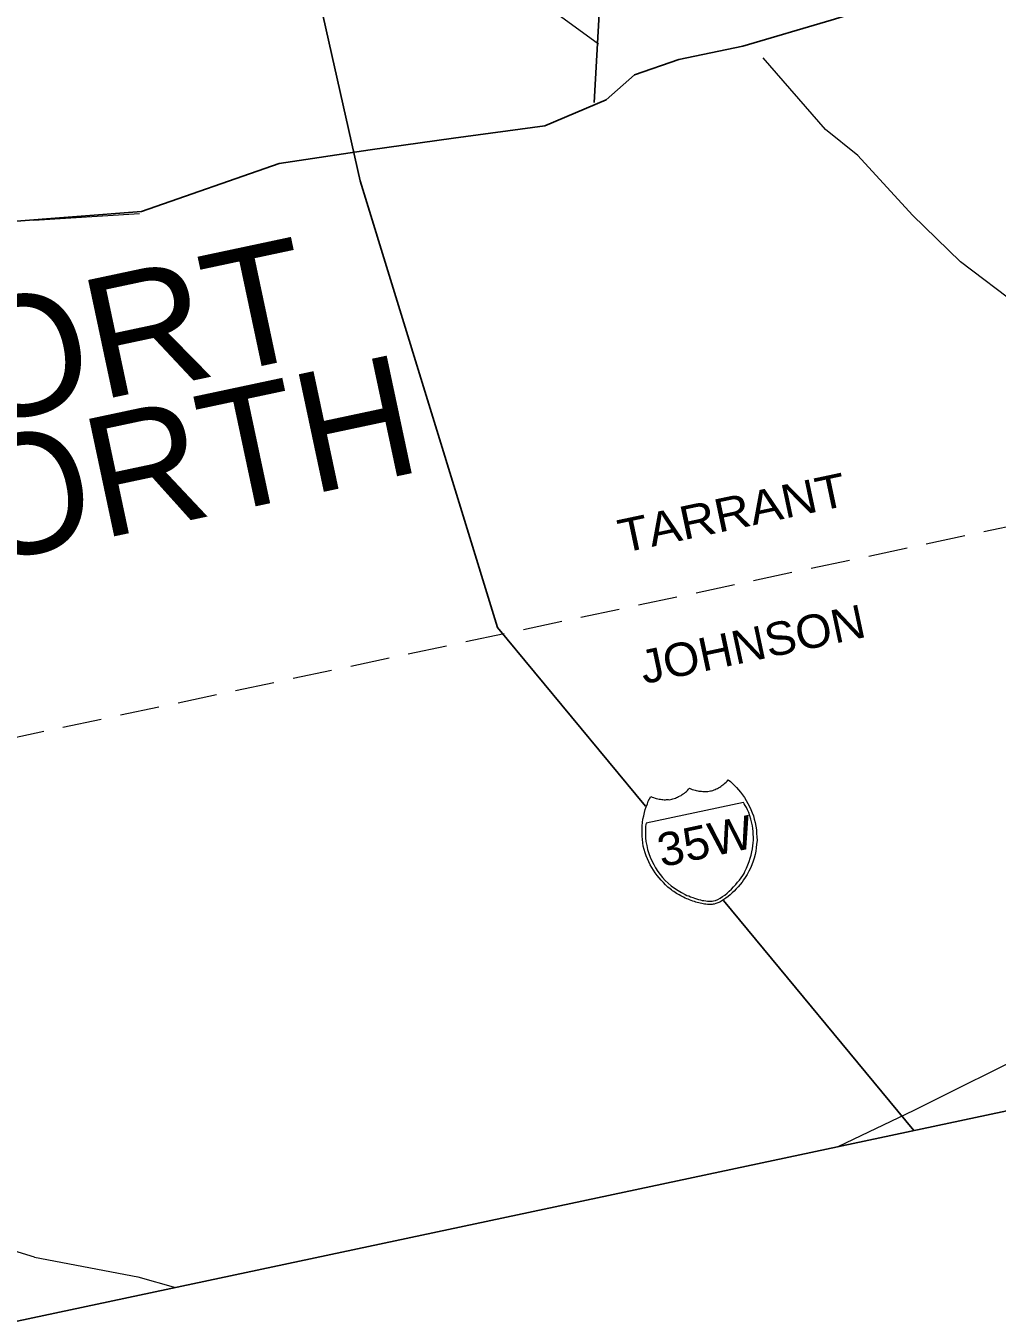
# Model space of a CAD drawing. Extents: x 2357218 to 2371708, y 6973728 to 6980157.
# Drawn here: x 2371385.2 to 2371533.8, y 6977387.6 to 6977585.2 of the extents above; entities that cross this region are included whole.
import ezdxf

# ---------------------------------------------------------------- set-up
doc = ezdxf.new("R2010")
doc.units = 0
doc.header["$LTSCALE"] = 2
doc.linetypes.add('MEDIUM_DASHED', pattern=[4.5, 3, -1.5])
doc.layers.add('62', color=7, linetype='Continuous', lineweight=13)
doc.layers.add('63', color=7, linetype='Continuous', lineweight=13)

msp = doc.modelspace()

# ---------------------------------------------------------------- linework, layer by layer
at = {"layer": '62', "lineweight": 25}
for p, q in [((2371472.934, 6977588.003), (2371472.125, 6977573.525)), ((2371491.914, 6977451.41), (2371521.051, 6977416.173))]:
    msp.add_line(p, q, dxfattribs=at)
at = {"layer": '62'}
for p, q in [((2371402.615, 6977556.471), (2371386.454, 6977555.453)), ((2371386.545, 6977396.784), (2371375.178, 6977400.278))]:
    msp.add_line(p, q, dxfattribs=at)
at = {"layer": '62', "linetype": 'MEDIUM_DASHED'}
msp.add_line((2371250.037, 6977447.964), (2371689.806, 6977541.441), dxfattribs=at)
at = {"layer": '62', "lineweight": 25}
for points in [[(2371171.482, 6977817.538), (2371268.218, 6977362.432), (2371707.985, 6977455.907), (2371611.249, 6977911.015)], [(2371413.016, 6977663.491), (2371424.115, 6977615.928), (2371436.376, 6977561.509), (2371457.345, 6977493.157), (2371479.97, 6977465.828)], [(2371525.33, 6977592.147), (2371517.989, 6977589.024), (2371508.4, 6977586.087), (2371494.884, 6977582.133), (2371485.112, 6977580.058), (2371478.295, 6977577.711), (2371473.995, 6977573.922), (2371464.607, 6977569.925), (2371450.652, 6977568.04), (2371437.897, 6977566.249), (2371423.963, 6977564.162), (2371402.89, 6977556.805), (2371381.813, 6977555.202), (2371364.473, 6977555.496), (2371353.545, 6977558.763), (2371347.781, 6977571.044), (2371345.031, 6977583.983), (2371341.826, 6977589.973), (2371344.749, 6977600.141)]]:
    msp.add_lwpolyline(points, dxfattribs=at)
at = {"layer": '62'}
for points in [[(2371472.829, 6977582.438), (2371452.543, 6977597.245), (2371424.668, 6977617.014)], [(2371640.114, 6977493.057), (2371631.587, 6977494.329), (2371621.782, 6977494.129), (2371604.117, 6977494.011), (2371592.783, 6977497.996), (2371585.105, 6977500.871), (2371575.158, 6977504.807), (2371564.602, 6977512.159), (2371556.475, 6977520.853), (2371548.287, 6977530.798), (2371537.195, 6977542.291), (2371528.149, 6977549.131), (2371520.811, 6977556.266), (2371512.448, 6977565.414), (2371507.538, 6977569.364), (2371497.978, 6977580.353)], [(2371641.471, 6977568.825), (2371637.889, 6977558.952), (2371632.104, 6977540.699), (2371630.059, 6977521.101), (2371629.958, 6977506.428), (2371616.354, 6977490.125), (2371618.311, 6977480.254), (2371604.289, 6977467.66), (2371593.247, 6977456.295), (2371579.034, 6977445.889), (2371557.99, 6977437.089), (2371540.234, 6977428.852), (2371521.019, 6977419.249), (2371509.386, 6977413.693)], [(2371487.57, 6977468.272), (2371487.767, 6977468.22), (2371487.983, 6977468.173), (2371488.151, 6977468.142), (2371488.368, 6977468.096), (2371488.575, 6977468.093), (2371488.765, 6977468.066), (2371488.95, 6977468.059), (2371489.152, 6977468.079), (2371489.338, 6977468.073), (2371489.547, 6977468.07), (2371489.723, 6977468.108), (2371489.922, 6977468.15), (2371490.097, 6977468.186), (2371490.271, 6977468.224), (2371490.482, 6977468.316), (2371490.628, 6977468.391), (2371490.799, 6977468.452), (2371490.987, 6977468.536), (2371491.172, 6977468.647), (2371491.339, 6977468.727), (2371491.518, 6977468.856), (2371491.68, 6977468.959), (2371491.838, 6977469.085), (2371491.995, 6977469.21), (2371492.153, 6977469.336), (2371492.326, 6977469.489), (2371492.496, 6977469.664), (2371492.646, 6977469.833), (2371492.973, 6977469.582), (2371493.288, 6977469.303), (2371493.604, 6977469.002), (2371493.928, 6977468.657), (2371494.231, 6977468.33), (2371494.539, 6977467.959), (2371494.832, 6977467.56), (2371495.128, 6977467.139), (2371495.407, 6977466.695), (2371495.664, 6977466.242), (2371495.901, 6977465.763), (2371496.115, 6977465.304), (2371496.311, 6977464.816), (2371496.507, 6977464.328), (2371496.638, 6977463.826), (2371496.791, 6977463.329), (2371496.863, 6977462.77), (2371496.956, 6977462.213), (2371496.987, 6977461.645), (2371497.026, 6977461.124), (2371497.053, 6977460.577), (2371496.989, 6977460.012), (2371496.942, 6977459.471), (2371496.869, 6977458.951), (2371496.751, 6977458.418), (2371496.613, 6977457.885), (2371496.443, 6977457.387), (2371496.275, 6977456.868), (2371496.04, 6977456.358), (2371495.796, 6977455.871), (2371495.535, 6977455.376), (2371495.222, 6977454.897), (2371495.001, 6977454.528), (2371494.755, 6977454.178), (2371494.462, 6977453.816), (2371494.187, 6977453.481), (2371493.865, 6977453.16), (2371493.541, 6977452.838), (2371493.236, 6977452.542), (2371492.932, 6977452.248), (2371492.622, 6977451.976), (2371492.303, 6977451.745), (2371491.984, 6977451.517), (2371491.662, 6977451.31), (2371491.369, 6977451.156), (2371491.076, 6977451.026), (2371490.776, 6977450.916), (2371490.517, 6977450.836)], [(2371490.517, 6977450.836), (2371490.336, 6977450.823), (2371490.183, 6977450.79), (2371490.003, 6977450.773), (2371489.841, 6977450.786), (2371489.653, 6977450.793), (2371489.468, 6977450.798), (2371489.233, 6977450.818), (2371489.02, 6977450.84), (2371488.827, 6977450.891), (2371488.615, 6977450.917), (2371488.369, 6977450.978), (2371488.152, 6977451.024), (2371487.914, 6977451.067), (2371487.717, 6977451.138), (2371487.466, 6977451.225), (2371487.223, 6977451.288), (2371486.998, 6977451.378), (2371486.748, 6977451.464), (2371486.52, 6977451.575), (2371486.293, 6977451.663), (2371486.065, 6977451.755), (2371485.832, 6977451.889), (2371485.604, 6977451.979), (2371485.395, 6977452.096), (2371485.16, 6977452.23), (2371484.951, 6977452.346), (2371484.743, 6977452.461), (2371484.551, 6977452.606), (2371484.316, 6977452.74), (2371484.129, 6977452.859), (2371483.958, 6977453.009), (2371483.768, 6977453.153), (2371483.429, 6977453.449), (2371483.052, 6977453.807), (2371482.728, 6977454.15), (2371482.403, 6977454.496), (2371482.072, 6977454.862), (2371481.762, 6977455.232), (2371481.475, 6977455.608), (2371481.227, 6977456.017), (2371480.957, 6977456.42), (2371480.705, 6977456.849), (2371480.513, 6977457.315), (2371480.306, 6977457.754), (2371480.091, 6977458.214), (2371479.95, 6977458.669), (2371479.794, 6977459.188), (2371479.661, 6977459.688), (2371479.6, 6977460.207), (2371479.536, 6977460.721), (2371479.495, 6977461.241), (2371479.473, 6977461.766), (2371479.482, 6977462.274), (2371479.507, 6977462.808), (2371479.557, 6977463.324), (2371479.609, 6977463.842), (2371479.731, 6977464.351), (2371479.833, 6977464.833), (2371479.966, 6977465.297), (2371480.105, 6977465.719), (2371480.287, 6977466.174), (2371480.41, 6977466.564), (2371480.604, 6977466.951), (2371480.802, 6977467.316), (2371481.006, 6977467.222), (2371481.232, 6977467.131), (2371481.456, 6977467.062), (2371481.65, 6977467.011), (2371481.867, 6977466.965), (2371482.061, 6977466.917), (2371482.273, 6977466.891), (2371482.469, 6977466.842), (2371482.653, 6977466.836), (2371482.843, 6977466.807), (2371483.05, 6977466.805), (2371483.231, 6977466.819), (2371483.463, 6977466.824), (2371483.625, 6977466.811), (2371483.801, 6977466.848), (2371484.02, 6977466.896), (2371484.196, 6977466.933), (2371484.372, 6977466.97), (2371484.561, 6977467.056), (2371484.727, 6977467.137), (2371484.899, 6977467.198), (2371485.065, 6977467.279), (2371485.272, 6977467.393), (2371485.441, 6977467.473), (2371485.598, 6977467.599), (2371485.76, 6977467.703), (2371485.939, 6977467.833), (2371486.118, 6977467.963), (2371486.275, 6977468.089), (2371486.428, 6977468.235), (2371486.578, 6977468.404), (2371486.746, 6977468.578), (2371486.95, 6977468.485), (2371487.154, 6977468.39), (2371487.377, 6977468.323), (2371487.57, 6977468.272)], [(2371386.545, 6977396.784), (2371402.342, 6977393.793), (2371408.116, 6977392.167)]]:
    msp.add_lwpolyline(points, dxfattribs=at)
msp.add_lwpolyline([(2371494.987, 6977466.398), (2371480.084, 6977463.229), (2371480.045, 6977462.992), (2371480.016, 6977462.687), (2371479.993, 6977462.361), (2371479.99, 6977461.943), (2371479.974, 6977461.48), (2371479.993, 6977460.957), (2371480.06, 6977460.419), (2371480.19, 6977459.799), (2371480.32, 6977459.207), (2371480.499, 6977458.576), (2371480.713, 6977458.002), (2371480.971, 6977457.435), (2371481.251, 6977456.873), (2371481.544, 6977456.361), (2371481.864, 6977455.83), (2371482.24, 6977455.358), (2371482.612, 6977454.909), (2371483.007, 6977454.463), (2371483.467, 6977454.031), (2371483.92, 6977453.623), (2371484.432, 6977453.272), (2371484.966, 6977452.923), (2371485.49, 6977452.62), (2371486.059, 6977452.329), (2371486.321, 6977452.176), (2371486.618, 6977452.078), (2371486.902, 6977451.932), (2371487.221, 6977451.838), (2371487.498, 6977451.735), (2371487.797, 6977451.617), (2371488.085, 6977451.564), (2371488.382, 6977451.465), (2371488.669, 6977451.41), (2371488.93, 6977451.375), (2371489.22, 6977451.32), (2371489.458, 6977451.279), (2371489.734, 6977451.268), (2371489.964, 6977451.272), (2371490.19, 6977451.298), (2371490.416, 6977451.323), (2371490.72, 6977451.41), (2371491.078, 6977451.554), (2371491.402, 6977451.761), (2371491.771, 6977451.979), (2371492.11, 6977452.211), (2371492.465, 6977452.495), (2371492.794, 6977452.794), (2371493.138, 6977453.118), (2371493.478, 6977453.469), (2371493.791, 6977453.834), (2371494.088, 6977454.172), (2371494.362, 6977454.506), (2371494.637, 6977454.84), (2371494.861, 6977455.188), (2371495.064, 6977455.531), (2371495.189, 6977455.811), (2371495.443, 6977456.348), (2371495.635, 6977456.849), (2371495.827, 6977457.348), (2371495.993, 6977457.866), (2371496.146, 6977458.338), (2371496.254, 6977458.821), (2371496.34, 6977459.274), (2371496.401, 6977459.748), (2371496.464, 6977460.199), (2371496.509, 6977460.644), (2371496.51, 6977461.083), (2371496.481, 6977461.535), (2371496.456, 6977461.969), (2371496.413, 6977462.396), (2371496.345, 6977462.821), (2371496.261, 6977463.215), (2371496.129, 6977463.834), (2371495.974, 6977464.351), (2371495.778, 6977464.841), (2371495.619, 6977465.265), (2371495.425, 6977465.639), (2371495.247, 6977465.925), (2371495.099, 6977466.192)], close=True, dxfattribs=at)
at = {"layer": '63', "lineweight": 25}
for p, q in [((2371472.934, 6977588.003), (2371472.125, 6977573.525)), ((2371491.914, 6977451.41), (2371521.051, 6977416.173))]:
    msp.add_line(p, q, dxfattribs=at)
at = {"layer": '63'}
for p, q in [((2371402.615, 6977556.471), (2371386.454, 6977555.453)), ((2371386.545, 6977396.784), (2371375.178, 6977400.278))]:
    msp.add_line(p, q, dxfattribs=at)
at = {"layer": '63', "linetype": 'MEDIUM_DASHED'}
msp.add_line((2371250.037, 6977447.964), (2371689.806, 6977541.441), dxfattribs=at)
at = {"layer": '63', "lineweight": 25}
for points in [[(2371171.482, 6977817.538), (2371268.218, 6977362.432), (2371707.985, 6977455.907), (2371611.249, 6977911.015)], [(2371413.016, 6977663.491), (2371424.115, 6977615.928), (2371436.376, 6977561.509), (2371457.345, 6977493.157), (2371479.97, 6977465.828)], [(2371525.33, 6977592.147), (2371517.989, 6977589.024), (2371508.4, 6977586.087), (2371494.884, 6977582.133), (2371485.112, 6977580.058), (2371478.295, 6977577.711), (2371473.995, 6977573.922), (2371464.607, 6977569.925), (2371450.652, 6977568.04), (2371437.897, 6977566.249), (2371423.963, 6977564.162), (2371402.89, 6977556.805), (2371381.813, 6977555.202), (2371364.473, 6977555.496), (2371353.545, 6977558.763), (2371347.781, 6977571.044), (2371345.031, 6977583.983), (2371341.826, 6977589.973), (2371344.749, 6977600.141)]]:
    msp.add_lwpolyline(points, dxfattribs=at)
at = {"layer": '63'}
for points in [[(2371472.829, 6977582.438), (2371452.543, 6977597.245), (2371424.668, 6977617.014)], [(2371640.114, 6977493.057), (2371631.587, 6977494.329), (2371621.782, 6977494.129), (2371604.117, 6977494.011), (2371592.783, 6977497.996), (2371585.105, 6977500.871), (2371575.158, 6977504.807), (2371564.602, 6977512.159), (2371556.475, 6977520.853), (2371548.287, 6977530.798), (2371537.195, 6977542.291), (2371528.149, 6977549.131), (2371520.811, 6977556.266), (2371512.448, 6977565.414), (2371507.538, 6977569.364), (2371497.978, 6977580.353)], [(2371641.471, 6977568.825), (2371637.889, 6977558.952), (2371632.104, 6977540.699), (2371630.059, 6977521.101), (2371629.958, 6977506.428), (2371616.354, 6977490.125), (2371618.311, 6977480.254), (2371604.289, 6977467.66), (2371593.247, 6977456.295), (2371579.034, 6977445.889), (2371557.99, 6977437.089), (2371540.234, 6977428.852), (2371521.019, 6977419.249), (2371509.386, 6977413.693)], [(2371487.57, 6977468.272), (2371487.767, 6977468.22), (2371487.983, 6977468.173), (2371488.151, 6977468.142), (2371488.368, 6977468.096), (2371488.575, 6977468.093), (2371488.765, 6977468.066), (2371488.95, 6977468.059), (2371489.152, 6977468.079), (2371489.338, 6977468.073), (2371489.547, 6977468.07), (2371489.723, 6977468.108), (2371489.922, 6977468.15), (2371490.097, 6977468.186), (2371490.271, 6977468.224), (2371490.482, 6977468.316), (2371490.628, 6977468.391), (2371490.799, 6977468.452), (2371490.987, 6977468.536), (2371491.172, 6977468.647), (2371491.339, 6977468.727), (2371491.518, 6977468.856), (2371491.68, 6977468.959), (2371491.838, 6977469.085), (2371491.995, 6977469.21), (2371492.153, 6977469.336), (2371492.326, 6977469.489), (2371492.496, 6977469.664), (2371492.646, 6977469.833), (2371492.973, 6977469.582), (2371493.288, 6977469.303), (2371493.604, 6977469.002), (2371493.928, 6977468.657), (2371494.231, 6977468.33), (2371494.539, 6977467.959), (2371494.832, 6977467.56), (2371495.128, 6977467.139), (2371495.407, 6977466.695), (2371495.664, 6977466.242), (2371495.901, 6977465.763), (2371496.115, 6977465.304), (2371496.311, 6977464.816), (2371496.507, 6977464.328), (2371496.638, 6977463.826), (2371496.791, 6977463.329), (2371496.863, 6977462.77), (2371496.956, 6977462.213), (2371496.987, 6977461.645), (2371497.026, 6977461.124), (2371497.053, 6977460.577), (2371496.989, 6977460.012), (2371496.942, 6977459.471), (2371496.869, 6977458.951), (2371496.751, 6977458.418), (2371496.613, 6977457.885), (2371496.443, 6977457.387), (2371496.275, 6977456.868), (2371496.04, 6977456.358), (2371495.796, 6977455.871), (2371495.535, 6977455.376), (2371495.222, 6977454.897), (2371495.001, 6977454.528), (2371494.755, 6977454.178), (2371494.462, 6977453.816), (2371494.187, 6977453.481), (2371493.865, 6977453.16), (2371493.541, 6977452.838), (2371493.236, 6977452.542), (2371492.932, 6977452.248), (2371492.622, 6977451.976), (2371492.303, 6977451.745), (2371491.984, 6977451.517), (2371491.662, 6977451.31), (2371491.369, 6977451.156), (2371491.076, 6977451.026), (2371490.776, 6977450.916), (2371490.517, 6977450.836)], [(2371490.517, 6977450.836), (2371490.336, 6977450.823), (2371490.183, 6977450.79), (2371490.003, 6977450.773), (2371489.841, 6977450.786), (2371489.653, 6977450.793), (2371489.468, 6977450.798), (2371489.233, 6977450.818), (2371489.02, 6977450.84), (2371488.827, 6977450.891), (2371488.615, 6977450.917), (2371488.369, 6977450.978), (2371488.152, 6977451.024), (2371487.914, 6977451.067), (2371487.717, 6977451.138), (2371487.466, 6977451.225), (2371487.223, 6977451.288), (2371486.998, 6977451.378), (2371486.748, 6977451.464), (2371486.52, 6977451.575), (2371486.293, 6977451.663), (2371486.065, 6977451.755), (2371485.832, 6977451.889), (2371485.604, 6977451.979), (2371485.395, 6977452.096), (2371485.16, 6977452.23), (2371484.951, 6977452.346), (2371484.743, 6977452.461), (2371484.551, 6977452.606), (2371484.316, 6977452.74), (2371484.129, 6977452.859), (2371483.958, 6977453.009), (2371483.768, 6977453.153), (2371483.429, 6977453.449), (2371483.052, 6977453.807), (2371482.728, 6977454.15), (2371482.403, 6977454.496), (2371482.072, 6977454.862), (2371481.762, 6977455.232), (2371481.475, 6977455.608), (2371481.227, 6977456.017), (2371480.957, 6977456.42), (2371480.705, 6977456.849), (2371480.513, 6977457.315), (2371480.306, 6977457.754), (2371480.091, 6977458.214), (2371479.95, 6977458.669), (2371479.794, 6977459.188), (2371479.661, 6977459.688), (2371479.6, 6977460.207), (2371479.536, 6977460.721), (2371479.495, 6977461.241), (2371479.473, 6977461.766), (2371479.482, 6977462.274), (2371479.507, 6977462.808), (2371479.557, 6977463.324), (2371479.609, 6977463.842), (2371479.731, 6977464.351), (2371479.833, 6977464.833), (2371479.966, 6977465.297), (2371480.105, 6977465.719), (2371480.287, 6977466.174), (2371480.41, 6977466.564), (2371480.604, 6977466.951), (2371480.802, 6977467.316), (2371481.006, 6977467.222), (2371481.232, 6977467.131), (2371481.456, 6977467.062), (2371481.65, 6977467.011), (2371481.867, 6977466.965), (2371482.061, 6977466.917), (2371482.273, 6977466.891), (2371482.469, 6977466.842), (2371482.653, 6977466.836), (2371482.843, 6977466.807), (2371483.05, 6977466.805), (2371483.231, 6977466.819), (2371483.463, 6977466.824), (2371483.625, 6977466.811), (2371483.801, 6977466.848), (2371484.02, 6977466.896), (2371484.196, 6977466.933), (2371484.372, 6977466.97), (2371484.561, 6977467.056), (2371484.727, 6977467.137), (2371484.899, 6977467.198), (2371485.065, 6977467.279), (2371485.272, 6977467.393), (2371485.441, 6977467.473), (2371485.598, 6977467.599), (2371485.76, 6977467.703), (2371485.939, 6977467.833), (2371486.118, 6977467.963), (2371486.275, 6977468.089), (2371486.428, 6977468.235), (2371486.578, 6977468.404), (2371486.746, 6977468.578), (2371486.95, 6977468.485), (2371487.154, 6977468.39), (2371487.377, 6977468.323), (2371487.57, 6977468.272)], [(2371386.545, 6977396.784), (2371402.342, 6977393.793), (2371408.116, 6977392.167)]]:
    msp.add_lwpolyline(points, dxfattribs=at)
msp.add_lwpolyline([(2371494.987, 6977466.398), (2371480.084, 6977463.229), (2371480.045, 6977462.992), (2371480.016, 6977462.687), (2371479.993, 6977462.361), (2371479.99, 6977461.943), (2371479.974, 6977461.48), (2371479.993, 6977460.957), (2371480.06, 6977460.419), (2371480.19, 6977459.799), (2371480.32, 6977459.207), (2371480.499, 6977458.576), (2371480.713, 6977458.002), (2371480.971, 6977457.435), (2371481.251, 6977456.873), (2371481.544, 6977456.361), (2371481.864, 6977455.83), (2371482.24, 6977455.358), (2371482.612, 6977454.909), (2371483.007, 6977454.463), (2371483.467, 6977454.031), (2371483.92, 6977453.623), (2371484.432, 6977453.272), (2371484.966, 6977452.923), (2371485.49, 6977452.62), (2371486.059, 6977452.329), (2371486.321, 6977452.176), (2371486.618, 6977452.078), (2371486.902, 6977451.932), (2371487.221, 6977451.838), (2371487.498, 6977451.735), (2371487.797, 6977451.617), (2371488.085, 6977451.564), (2371488.382, 6977451.465), (2371488.669, 6977451.41), (2371488.93, 6977451.375), (2371489.22, 6977451.32), (2371489.458, 6977451.279), (2371489.734, 6977451.268), (2371489.964, 6977451.272), (2371490.19, 6977451.298), (2371490.416, 6977451.323), (2371490.72, 6977451.41), (2371491.078, 6977451.554), (2371491.402, 6977451.761), (2371491.771, 6977451.979), (2371492.11, 6977452.211), (2371492.465, 6977452.495), (2371492.794, 6977452.794), (2371493.138, 6977453.118), (2371493.478, 6977453.469), (2371493.791, 6977453.834), (2371494.088, 6977454.172), (2371494.362, 6977454.506), (2371494.637, 6977454.84), (2371494.861, 6977455.188), (2371495.064, 6977455.531), (2371495.189, 6977455.811), (2371495.443, 6977456.348), (2371495.635, 6977456.849), (2371495.827, 6977457.348), (2371495.993, 6977457.866), (2371496.146, 6977458.338), (2371496.254, 6977458.821), (2371496.34, 6977459.274), (2371496.401, 6977459.748), (2371496.464, 6977460.199), (2371496.509, 6977460.644), (2371496.51, 6977461.083), (2371496.481, 6977461.535), (2371496.456, 6977461.969), (2371496.413, 6977462.396), (2371496.345, 6977462.821), (2371496.261, 6977463.215), (2371496.129, 6977463.834), (2371495.974, 6977464.351), (2371495.778, 6977464.841), (2371495.619, 6977465.265), (2371495.425, 6977465.639), (2371495.247, 6977465.925), (2371495.099, 6977466.192)], close=True, dxfattribs=at)

# ---------------------------------------------------------------- texts
at = {"layer": '62'}
for s, height, width, p in [('FORT', 18.39, 1.05, (2371361.431, 6977520.457)), ('TARRANT', 5.099, 1.1, (2371476.456, 6977504.534)), ('JOHNSON', 5.099, 1.05, (2371479.752, 6977484.484)), ('35W', 5.099, 1.05, (2371482.444, 6977456.459))]:
    msp.add_text(s, height=height, rotation=12, dxfattribs=dict(at, width=width)).set_placement(p)
msp.add_text('WORTH', height=18.39, rotation=12, dxfattribs=at).set_placement((2371355.347, 6977497.885))
at = {"layer": '63'}
for s, height, width, p in [('FORT', 18.39, 1.05, (2371361.431, 6977520.457)), ('TARRANT', 5.099, 1.1, (2371476.456, 6977504.534)), ('JOHNSON', 5.099, 1.05, (2371479.752, 6977484.484)), ('35W', 5.099, 1.05, (2371482.444, 6977456.459))]:
    msp.add_text(s, height=height, rotation=12, dxfattribs=dict(at, width=width)).set_placement(p)
msp.add_text('WORTH', height=18.39, rotation=12, dxfattribs=at).set_placement((2371355.347, 6977497.885))

doc.saveas('drawing.dxf')
